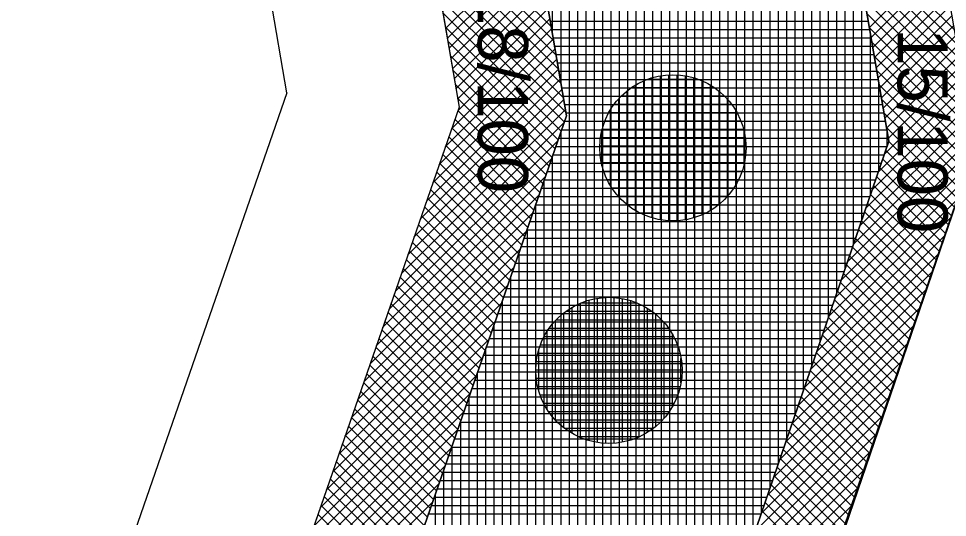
# Model space of a CAD drawing. Extents: x -565346 to -564154, y -1097386 to -1095620.
# Drawn here: x -564193.91 to -564171.69, y -1096311 to -1096299.05 of the extents above; entities that cross this region are included whole.
import ezdxf

# ---------------------------------------------------------------- set-up
doc = ezdxf.new("R2010")
doc.units = 0
for name, color, linetype in [('Vrstva 1', 7, 'Continuous'), ('Vrstva 13', 7, 'Continuous'), ('Vrstva 40', 7, 'Continuous'), ('Vrstva 41', 7, 'Continuous'), ('Vrstva 42', 7, 'Continuous'), ('Vrstva 43', 7, 'Continuous'), ('Vrstva 44', 7, 'Continuous')]:
    doc.layers.add(name, color=color, linetype=linetype)

msp = doc.modelspace()

# ---------------------------------------------------------------- linework, layer by layer
at = {"layer": 'Vrstva 1'}
for p, q in [((-564189.19, -1096267.23), (-564183.37, -1096301.17)), ((-564187.49, -1096300.83), (-564193.07, -1096268.27)), ((-564187.49, -1096300.83), (-564202.39, -1096343.85)), ((-564183.37, -1096301.17), (-564225.11, -1096421.68))]:
    msp.add_line(p, q, dxfattribs=at)
at = {"layer": 'Vrstva 13'}
msp.add_line((-564171.03, -1096302.15), (-564215.39, -1096431.76), dxfattribs=at)
at = {"layer": 'Vrstva 41'}
for points in [[(-564215.226, -1096425.104), (-564213.26, -1096425.74), (-564190.01, -1096357.19), (-564171.03, -1096302.15), (-564177.55, -1096264.11), (-564190.98, -1096227.75), (-564194.264, -1096223.181), (-564195.888, -1096224.348), (-564192.762, -1096228.697), (-564179.49, -1096264.63), (-564173.087, -1096301.985)], [(-564225.11, -1096421.68), (-564222.748, -1096422.498), (-564180.797, -1096301.38), (-564186.765, -1096266.582), (-564199.442, -1096232.246), (-564201.974, -1096228.723), (-564204.005, -1096230.182), (-564201.67, -1096233.43), (-564189.19, -1096267.23), (-564183.37, -1096301.17)]]:
    msp.add_lwpolyline(points, close=True, dxfattribs=at)
at = {"layer": 'Vrstva 42'}
for p, q in [((-564184.226, -1096296.179), (-564181.164, -1096299.241)), ((-564184.167, -1096296.52), (-564181.105, -1096299.582)), ((-564184.109, -1096296.862), (-564181.047, -1096299.924)), ((-564173.962, -1096296.881), (-564171.513, -1096299.329)), ((-564184.05, -1096297.203), (-564180.988, -1096300.265)), ((-564181.527, -1096297.122), (-564183.693, -1096299.287)), ((-564173.903, -1096297.222), (-564171.455, -1096299.67)), ((-564181.486, -1096297.363), (-564183.651, -1096299.529)), ((-564183.992, -1096297.545), (-564180.93, -1096300.607)), ((-564181.445, -1096297.604), (-564183.61, -1096299.77)), ((-564173.845, -1096297.563), (-564171.396, -1096300.012)), ((-564171.822, -1096297.529), (-564173.554, -1096299.261)), ((-564183.933, -1096297.886), (-564180.871, -1096300.948)), ((-564181.403, -1096297.846), (-564183.569, -1096300.011)), ((-564171.781, -1096297.77), (-564173.513, -1096299.502)), ((-564181.362, -1096298.087), (-564183.527, -1096300.253)), ((-564173.786, -1096297.905), (-564171.338, -1096300.353)), ((-564171.739, -1096298.012), (-564173.471, -1096299.744)), ((-564183.875, -1096298.227), (-564180.813, -1096301.289)), ((-564181.32, -1096298.329), (-564183.486, -1096300.494)), ((-564173.728, -1096298.246), (-564171.279, -1096300.695)), ((-564171.698, -1096298.253), (-564173.43, -1096299.985)), ((-564183.816, -1096298.569), (-564180.85, -1096301.534)), ((-564181.279, -1096298.57), (-564183.444, -1096300.736)), ((-564171.657, -1096298.495), (-564173.388, -1096300.227)), ((-564173.669, -1096298.587), (-564171.221, -1096301.036)), ((-564171.615, -1096298.736), (-564173.347, -1096300.468)), ((-564183.758, -1096298.91), (-564180.923, -1096301.744)), ((-564181.237, -1096298.812), (-564183.403, -1096300.977)), ((-564173.611, -1096298.929), (-564171.162, -1096301.377)), ((-564171.574, -1096298.978), (-564173.306, -1096300.709)), ((-564181.196, -1096299.053), (-564183.4, -1096301.257)), ((-564171.532, -1096299.219), (-564173.264, -1096300.951)), ((-564183.699, -1096299.251), (-564180.996, -1096301.954)), ((-564181.155, -1096299.295), (-564183.55, -1096301.69)), ((-564173.552, -1096299.27), (-564171.104, -1096301.719)), ((-564181.113, -1096299.536), (-564183.7, -1096302.123)), ((-564183.64, -1096299.593), (-564181.069, -1096302.165)), ((-564173.494, -1096299.612), (-564171.045, -1096302.06)), ((-564171.491, -1096299.461), (-564173.223, -1096301.192)), ((-564181.072, -1096299.777), (-564183.85, -1096302.555)), ((-564171.45, -1096299.702), (-564173.181, -1096301.434)), ((-564181.03, -1096300.019), (-564184, -1096302.988)), ((-564183.582, -1096299.934), (-564181.142, -1096302.375)), ((-564173.435, -1096299.953), (-564171.083, -1096302.305)), ((-564171.408, -1096299.943), (-564173.14, -1096301.675)), ((-564180.989, -1096300.26), (-564184.15, -1096303.421)), ((-564183.523, -1096300.276), (-564181.214, -1096302.585)), ((-564173.377, -1096300.294), (-564171.156, -1096302.515)), ((-564171.367, -1096300.185), (-564173.099, -1096301.917)), ((-564180.948, -1096300.502), (-564184.299, -1096303.854)), ((-564171.325, -1096300.426), (-564173.193, -1096302.293)), ((-564180.906, -1096300.743), (-564184.449, -1096304.286)), ((-564183.465, -1096300.617), (-564181.287, -1096302.795)), ((-564171.284, -1096300.668), (-564173.34, -1096302.724)), ((-564173.318, -1096300.636), (-564171.228, -1096302.725)), ((-564180.865, -1096300.985), (-564184.599, -1096304.719)), ((-564183.406, -1096300.958), (-564181.36, -1096303.005)), ((-564171.243, -1096300.909), (-564173.487, -1096303.154)), ((-564173.26, -1096300.977), (-564171.301, -1096302.936)), ((-564180.823, -1096301.226), (-564184.749, -1096305.152)), ((-564171.201, -1096301.151), (-564173.634, -1096303.584)), ((-564183.398, -1096301.25), (-564181.433, -1096303.215)), ((-564171.16, -1096301.392), (-564173.781, -1096304.014)), ((-564173.201, -1096301.318), (-564171.373, -1096303.146)), ((-564180.851, -1096301.537), (-564184.899, -1096305.584)), ((-564183.543, -1096301.67), (-564181.578, -1096303.635)), ((-564183.47, -1096301.46), (-564181.505, -1096303.425)), ((-564171.119, -1096301.634), (-564173.928, -1096304.444)), ((-564173.143, -1096301.66), (-564171.446, -1096303.356)), ((-564183.616, -1096301.88), (-564181.651, -1096303.845)), ((-564171.077, -1096301.875), (-564174.076, -1096304.874)), ((-564181.001, -1096301.969), (-564185.049, -1096306.017)), ((-564183.689, -1096302.09), (-564181.724, -1096304.055)), ((-564171.036, -1096302.117), (-564174.223, -1096305.304)), ((-564173.09, -1096301.995), (-564171.519, -1096303.567)), ((-564183.761, -1096302.3), (-564181.796, -1096304.265)), ((-564173.163, -1096302.206), (-564171.591, -1096303.777)), ((-564181.151, -1096302.402), (-564185.199, -1096306.45)), ((-564183.834, -1096302.51), (-564181.869, -1096304.475)), ((-564171.158, -1096302.522), (-564174.37, -1096305.734)), ((-564173.235, -1096302.416), (-564171.664, -1096303.987)), ((-564183.907, -1096302.72), (-564181.942, -1096304.685)), ((-564173.307, -1096302.627), (-564171.736, -1096304.198)), ((-564181.301, -1096302.835), (-564185.349, -1096306.883)), ((-564183.98, -1096302.93), (-564182.015, -1096304.896)), ((-564171.307, -1096302.954), (-564174.517, -1096306.164)), ((-564173.379, -1096302.838), (-564171.809, -1096304.408)), ((-564184.053, -1096303.141), (-564182.087, -1096305.106)), ((-564173.451, -1096303.048), (-564171.881, -1096304.618)), ((-564181.451, -1096303.268), (-564185.499, -1096307.315)), ((-564184.125, -1096303.351), (-564182.16, -1096305.316)), ((-564171.456, -1096303.385), (-564174.664, -1096306.594)), ((-564173.523, -1096303.259), (-564171.954, -1096304.829)), ((-564184.198, -1096303.561), (-564182.233, -1096305.526)), ((-564173.667, -1096303.681), (-564172.099, -1096305.249)), ((-564173.595, -1096303.47), (-564172.026, -1096305.039)), ((-564181.601, -1096303.7), (-564185.648, -1096307.748)), ((-564184.271, -1096303.771), (-564182.306, -1096305.736)), ((-564171.605, -1096303.817), (-564174.812, -1096307.024)), ((-564173.739, -1096303.891), (-564172.171, -1096305.46)), ((-564184.344, -1096303.981), (-564182.378, -1096305.946)), ((-564173.812, -1096304.102), (-564172.244, -1096305.67)), ((-564181.751, -1096304.133), (-564185.798, -1096308.181)), ((-564184.416, -1096304.191), (-564182.451, -1096306.156)), ((-564171.754, -1096304.249), (-564174.959, -1096307.454)), ((-564173.884, -1096304.313), (-564172.316, -1096305.88)), ((-564181.9, -1096304.566), (-564185.948, -1096308.614)), ((-564184.489, -1096304.401), (-564182.524, -1096306.366)), ((-564173.956, -1096304.524), (-564172.389, -1096306.091)), ((-564184.562, -1096304.611), (-564182.597, -1096306.576)), ((-564171.903, -1096304.68), (-564175.106, -1096307.884)), ((-564174.028, -1096304.734), (-564172.461, -1096306.301)), ((-564182.05, -1096304.999), (-564186.098, -1096309.046)), ((-564184.635, -1096304.821), (-564182.67, -1096306.786)), ((-564174.1, -1096304.945), (-564172.534, -1096306.511)), ((-564184.707, -1096305.031), (-564182.742, -1096306.996)), ((-564172.051, -1096305.112), (-564175.253, -1096308.314)), ((-564174.172, -1096305.156), (-564172.606, -1096306.721)), ((-564182.2, -1096305.431), (-564186.248, -1096309.479)), ((-564184.853, -1096305.451), (-564182.888, -1096307.417)), ((-564184.78, -1096305.241), (-564182.815, -1096307.206)), ((-564174.244, -1096305.366), (-564172.679, -1096306.932)), ((-564184.926, -1096305.662), (-564182.961, -1096307.627)), ((-564172.2, -1096305.544), (-564175.4, -1096308.744)), ((-564174.316, -1096305.577), (-564172.751, -1096307.142)), ((-564182.35, -1096305.864), (-564186.398, -1096309.912)), ((-564184.998, -1096305.872), (-564183.033, -1096307.837)), ((-564174.389, -1096305.788), (-564172.824, -1096307.352)), ((-564185.071, -1096306.082), (-564183.106, -1096308.047)), ((-564172.349, -1096305.976), (-564175.547, -1096309.174)), ((-564174.461, -1096305.999), (-564172.897, -1096307.563)), ((-564182.5, -1096306.297), (-564186.548, -1096310.344)), ((-564185.144, -1096306.292), (-564183.179, -1096308.257)), ((-564174.533, -1096306.209), (-564172.969, -1096307.773)), ((-564185.217, -1096306.502), (-564183.252, -1096308.467)), ((-564172.498, -1096306.407), (-564175.695, -1096309.604)), ((-564174.605, -1096306.42), (-564173.042, -1096307.983)), ((-564182.65, -1096306.729), (-564186.698, -1096310.777)), ((-564185.29, -1096306.712), (-564183.324, -1096308.677)), ((-564174.677, -1096306.631), (-564173.114, -1096308.194)), ((-564185.362, -1096306.922), (-564183.397, -1096308.887)), ((-564172.647, -1096306.839), (-564175.842, -1096310.034)), ((-564174.749, -1096306.841), (-564173.187, -1096308.404)), ((-564182.8, -1096307.162), (-564186.847, -1096311.21)), ((-564185.435, -1096307.132), (-564183.47, -1096309.097)), ((-564174.821, -1096307.052), (-564173.259, -1096308.614)), ((-564185.508, -1096307.342), (-564183.543, -1096309.307)), ((-564172.796, -1096307.271), (-564175.989, -1096310.464)), ((-564174.893, -1096307.263), (-564173.332, -1096308.825)), ((-564182.95, -1096307.595), (-564186.997, -1096311.643)), ((-564185.581, -1096307.552), (-564183.615, -1096309.517)), ((-564174.966, -1096307.474), (-564173.404, -1096309.035)), ((-564185.653, -1096307.762), (-564183.688, -1096309.727)), ((-564172.945, -1096307.702), (-564176.136, -1096310.894)), ((-564175.11, -1096307.895), (-564173.549, -1096309.456)), ((-564175.038, -1096307.684), (-564173.477, -1096309.245)), ((-564183.099, -1096308.028), (-564187.147, -1096312.075)), ((-564185.726, -1096307.972), (-564183.761, -1096309.937)), ((-564175.182, -1096308.106), (-564173.622, -1096309.666)), ((-564185.799, -1096308.182), (-564183.834, -1096310.148)), ((-564173.094, -1096308.134), (-564176.283, -1096311.324)), ((-564175.254, -1096308.317), (-564173.694, -1096309.876)), ((-564183.249, -1096308.46), (-564187.297, -1096312.508)), ((-564185.872, -1096308.393), (-564183.907, -1096310.358)), ((-564173.242, -1096308.566), (-564176.431, -1096311.754)), ((-564175.326, -1096308.527), (-564173.767, -1096310.087)), ((-564185.944, -1096308.603), (-564183.979, -1096310.568)), ((-564175.398, -1096308.738), (-564173.839, -1096310.297)), ((-564183.399, -1096308.893), (-564187.447, -1096312.941)), ((-564186.017, -1096308.813), (-564184.052, -1096310.778)), ((-564173.391, -1096308.998), (-564176.578, -1096312.184)), ((-564175.47, -1096308.949), (-564173.912, -1096310.507)), ((-564186.163, -1096309.233), (-564184.198, -1096311.198)), ((-564186.09, -1096309.023), (-564184.125, -1096310.988)), ((-564175.543, -1096309.159), (-564173.984, -1096310.718)), ((-564183.549, -1096309.326), (-564187.597, -1096313.373)), ((-564186.235, -1096309.443), (-564184.27, -1096311.408)), ((-564173.54, -1096309.429), (-564176.725, -1096312.614)), ((-564175.615, -1096309.37), (-564174.057, -1096310.928)), ((-564186.308, -1096309.653), (-564184.343, -1096311.618)), ((-564175.687, -1096309.581), (-564174.129, -1096311.138)), ((-564183.699, -1096309.758), (-564187.747, -1096313.806)), ((-564186.381, -1096309.863), (-564184.416, -1096311.828)), ((-564173.689, -1096309.861), (-564176.872, -1096313.044)), ((-564175.759, -1096309.792), (-564174.202, -1096311.348)), ((-564186.454, -1096310.073), (-564184.489, -1096312.038)), ((-564175.831, -1096310.002), (-564174.275, -1096311.559)), ((-564183.849, -1096310.191), (-564187.897, -1096314.239)), ((-564186.526, -1096310.283), (-564184.561, -1096312.248)), ((-564173.838, -1096310.293), (-564177.019, -1096313.474)), ((-564175.903, -1096310.213), (-564174.347, -1096311.769)), ((-564186.599, -1096310.493), (-564184.634, -1096312.458)), ((-564175.975, -1096310.424), (-564174.42, -1096311.979)), ((-564183.999, -1096310.624), (-564188.046, -1096314.672)), ((-564186.672, -1096310.703), (-564184.707, -1096312.668)), ((-564173.987, -1096310.724), (-564177.166, -1096313.904)), ((-564176.047, -1096310.634), (-564174.492, -1096312.19)), ((-564186.745, -1096310.913), (-564184.78, -1096312.879)), ((-564176.119, -1096310.845), (-564174.565, -1096312.4))]:
    msp.add_line(p, q, dxfattribs=at)
at = {"layer": 'Vrstva 43'}
for p, q in [((-564181.13, -1096299.438), (-564181.13, -1096260.19)), ((-564180.93, -1096300.605), (-564180.93, -1096260.731)), ((-564180.73, -1096324.316), (-564180.73, -1096261.273)), ((-564180.53, -1096323.731), (-564180.53, -1096261.814)), ((-564180.33, -1096323.147), (-564180.33, -1096262.356)), ((-564180.13, -1096322.563), (-564180.13, -1096262.897)), ((-564179.93, -1096321.978), (-564179.93, -1096263.439)), ((-564179.73, -1096321.394), (-564179.73, -1096263.98)), ((-564179.53, -1096320.81), (-564179.53, -1096264.522)), ((-564179.33, -1096320.225), (-564179.33, -1096265.563)), ((-564179.13, -1096319.641), (-564179.13, -1096266.73)), ((-564178.93, -1096319.057), (-564178.93, -1096267.897)), ((-564178.73, -1096318.472), (-564178.73, -1096269.064)), ((-564178.53, -1096317.888), (-564178.53, -1096270.231)), ((-564178.33, -1096317.304), (-564178.33, -1096271.397)), ((-564178.13, -1096316.719), (-564178.13, -1096272.564)), ((-564177.93, -1096316.135), (-564177.93, -1096273.731)), ((-564177.73, -1096315.551), (-564177.73, -1096274.898)), ((-564177.53, -1096314.966), (-564177.53, -1096276.065)), ((-564177.33, -1096314.382), (-564177.33, -1096277.231)), ((-564177.13, -1096313.798), (-564177.13, -1096278.398)), ((-564176.93, -1096313.213), (-564176.93, -1096279.565)), ((-564176.73, -1096312.629), (-564176.73, -1096280.732)), ((-564176.53, -1096312.045), (-564176.53, -1096281.899)), ((-564176.33, -1096311.46), (-564176.33, -1096283.065)), ((-564176.13, -1096310.876), (-564176.13, -1096284.232)), ((-564175.93, -1096310.291), (-564175.93, -1096285.399)), ((-564175.73, -1096309.707), (-564175.73, -1096286.566)), ((-564175.53, -1096309.123), (-564175.53, -1096287.733)), ((-564175.33, -1096308.538), (-564175.33, -1096288.899)), ((-564175.13, -1096307.954), (-564175.13, -1096290.066)), ((-564174.93, -1096307.37), (-564174.93, -1096291.233)), ((-564174.73, -1096306.785), (-564174.73, -1096292.4)), ((-564174.53, -1096306.201), (-564174.53, -1096293.567)), ((-564174.33, -1096305.617), (-564174.33, -1096294.733)), ((-564174.13, -1096305.032), (-564174.13, -1096295.9)), ((-564173.93, -1096304.448), (-564173.93, -1096297.067)), ((-564173.73, -1096303.864), (-564173.73, -1096298.234)), ((-564181.186, -1096299.11), (-564173.58, -1096299.11)), ((-564181.152, -1096299.31), (-564173.546, -1096299.31)), ((-564173.53, -1096303.279), (-564173.53, -1096299.401)), ((-564181.118, -1096299.51), (-564173.511, -1096299.51)), ((-564181.083, -1096299.71), (-564173.477, -1096299.71)), ((-564181.049, -1096299.91), (-564173.443, -1096299.91)), ((-564181.015, -1096300.11), (-564173.408, -1096300.11)), ((-564180.981, -1096300.31), (-564173.374, -1096300.31)), ((-564180.946, -1096300.51), (-564173.34, -1096300.51)), ((-564173.33, -1096302.695), (-564173.33, -1096300.567)), ((-564180.912, -1096300.71), (-564173.306, -1096300.71)), ((-564180.878, -1096300.91), (-564173.271, -1096300.91)), ((-564180.843, -1096301.11), (-564173.237, -1096301.11)), ((-564180.809, -1096301.31), (-564173.203, -1096301.31)), ((-564180.842, -1096301.51), (-564173.168, -1096301.51)), ((-564180.93, -1096324.9), (-564180.93, -1096301.764)), ((-564180.911, -1096301.71), (-564173.134, -1096301.71)), ((-564173.13, -1096302.111), (-564173.13, -1096301.734)), ((-564181.05, -1096302.11), (-564173.13, -1096302.11)), ((-564180.981, -1096301.91), (-564173.1, -1096301.91)), ((-564181.13, -1096325.485), (-564181.13, -1096302.341)), ((-564181.119, -1096302.31), (-564173.198, -1096302.31)), ((-564181.188, -1096302.51), (-564173.267, -1096302.51)), ((-564181.258, -1096302.71), (-564173.335, -1096302.71)), ((-564181.33, -1096326.069), (-564181.33, -1096302.919)), ((-564181.327, -1096302.91), (-564173.404, -1096302.91)), ((-564181.396, -1096303.11), (-564173.472, -1096303.11)), ((-564181.465, -1096303.31), (-564173.54, -1096303.31)), ((-564181.535, -1096303.51), (-564173.609, -1096303.51)), ((-564181.53, -1096326.653), (-564181.53, -1096303.496)), ((-564181.604, -1096303.71), (-564173.677, -1096303.71)), ((-564181.743, -1096304.11), (-564173.814, -1096304.11)), ((-564181.73, -1096327.238), (-564181.73, -1096304.074)), ((-564181.673, -1096303.91), (-564173.746, -1096303.91)), ((-564181.812, -1096304.31), (-564173.883, -1096304.31)), ((-564181.881, -1096304.51), (-564173.951, -1096304.51)), ((-564181.95, -1096304.71), (-564174.02, -1096304.71)), ((-564181.93, -1096327.822), (-564181.93, -1096304.651)), ((-564182.02, -1096304.91), (-564174.088, -1096304.91)), ((-564182.13, -1096328.406), (-564182.13, -1096305.229)), ((-564182.089, -1096305.11), (-564174.157, -1096305.11)), ((-564182.158, -1096305.31), (-564174.225, -1096305.31)), ((-564182.227, -1096305.51), (-564174.293, -1096305.51)), ((-564182.33, -1096328.991), (-564182.33, -1096305.806)), ((-564182.297, -1096305.71), (-564174.362, -1096305.71)), ((-564182.435, -1096306.11), (-564174.499, -1096306.11)), ((-564182.366, -1096305.91), (-564174.43, -1096305.91)), ((-564182.505, -1096306.31), (-564174.567, -1096306.31)), ((-564182.574, -1096306.51), (-564174.636, -1096306.51)), ((-564182.53, -1096329.575), (-564182.53, -1096306.383)), ((-564182.643, -1096306.71), (-564174.704, -1096306.71)), ((-564182.73, -1096330.159), (-564182.73, -1096306.961)), ((-564182.712, -1096306.91), (-564174.773, -1096306.91)), ((-564182.782, -1096307.11), (-564174.841, -1096307.11)), ((-564182.851, -1096307.31), (-564174.91, -1096307.31)), ((-564182.93, -1096330.744), (-564182.93, -1096307.538)), ((-564182.92, -1096307.51), (-564174.978, -1096307.51)), ((-564182.989, -1096307.71), (-564175.046, -1096307.71)), ((-564183.13, -1096331.328), (-564183.13, -1096308.116)), ((-564183.128, -1096308.11), (-564175.183, -1096308.11)), ((-564183.059, -1096307.91), (-564175.115, -1096307.91)), ((-564183.197, -1096308.31), (-564175.252, -1096308.31)), ((-564183.267, -1096308.51), (-564175.32, -1096308.51)), ((-564183.336, -1096308.71), (-564175.389, -1096308.71)), ((-564183.33, -1096331.912), (-564183.33, -1096308.693)), ((-564183.405, -1096308.91), (-564175.457, -1096308.91)), ((-564183.474, -1096309.11), (-564175.526, -1096309.11)), ((-564183.544, -1096309.31), (-564175.594, -1096309.31)), ((-564183.53, -1096332.497), (-564183.53, -1096309.271)), ((-564183.613, -1096309.51), (-564175.663, -1096309.51)), ((-564183.73, -1096333.081), (-564183.73, -1096309.848)), ((-564183.682, -1096309.71), (-564175.731, -1096309.71)), ((-564183.821, -1096310.11), (-564175.868, -1096310.11)), ((-564183.751, -1096309.91), (-564175.799, -1096309.91)), ((-564183.89, -1096310.31), (-564175.936, -1096310.31)), ((-564183.959, -1096310.51), (-564176.005, -1096310.51)), ((-564183.93, -1096333.665), (-564183.93, -1096310.425)), ((-564184.029, -1096310.71), (-564176.073, -1096310.71)), ((-564184.098, -1096310.91), (-564176.142, -1096310.91))]:
    msp.add_line(p, q, dxfattribs=at)
msp.add_lwpolyline([(-564186.765, -1096266.582), (-564180.797, -1096301.38), (-564222.748, -1096422.498), (-564225.11, -1096421.68), (-564223.32, -1096427.69), (-564219.79, -1096430.8), (-564216.6, -1096431.71), (-564215.39, -1096431.76), (-564213.26, -1096425.74), (-564215.226, -1096425.104), (-564173.087, -1096301.985), (-564179.49, -1096264.63)], dxfattribs=at)
at = {"layer": 'Vrstva 44'}
for p, q in [((-564178.95, -1096303.748), (-564178.95, -1096300.54)), ((-564178.85, -1096300.5), (-564177.66, -1096300.5)), ((-564178.75, -1096303.822), (-564178.75, -1096300.467)), ((-564178.55, -1096303.867), (-564178.55, -1096300.42)), ((-564178.35, -1096303.89), (-564178.35, -1096300.398)), ((-564178.15, -1096303.89), (-564178.15, -1096300.399)), ((-564177.95, -1096303.866), (-564177.95, -1096300.422)), ((-564177.75, -1096303.818), (-564177.75, -1096300.469)), ((-564177.55, -1096303.744), (-564177.55, -1096300.543)), ((-564179.35, -1096303.508), (-564179.35, -1096300.781)), ((-564179.239, -1096300.7), (-564177.267, -1096300.7)), ((-564179.15, -1096303.645), (-564179.15, -1096300.642)), ((-564177.35, -1096303.642), (-564177.35, -1096300.648)), ((-564177.15, -1096303.499), (-564177.15, -1096300.786)), ((-564179.55, -1096303.318), (-564179.55, -1096300.969)), ((-564179.483, -1096300.9), (-564177.023, -1096300.9)), ((-564176.95, -1096303.31), (-564176.95, -1096300.98)), ((-564179.658, -1096301.1), (-564176.852, -1096301.1)), ((-564179.785, -1096301.3), (-564176.721, -1096301.3)), ((-564179.75, -1096303.049), (-564179.75, -1096301.237)), ((-564176.75, -1096303.037), (-564176.75, -1096301.253)), ((-564179.879, -1096301.5), (-564176.629, -1096301.5)), ((-564179.986, -1096301.9), (-564176.522, -1096301.9)), ((-564179.95, -1096302.572), (-564179.95, -1096301.713)), ((-564179.946, -1096301.7), (-564176.563, -1096301.7)), ((-564176.55, -1096302.534), (-564176.55, -1096301.749)), ((-564180.002, -1096302.1), (-564176.505, -1096302.1)), ((-564179.995, -1096302.3), (-564176.512, -1096302.3)), ((-564179.966, -1096302.5), (-564176.543, -1096302.5)), ((-564179.913, -1096302.7), (-564176.597, -1096302.7)), ((-564179.831, -1096302.9), (-564176.676, -1096302.9)), ((-564179.718, -1096303.1), (-564176.79, -1096303.1)), ((-564179.567, -1096303.3), (-564176.942, -1096303.3)), ((-564179.359, -1096303.5), (-564177.151, -1096303.5)), ((-564179.055, -1096303.7), (-564177.457, -1096303.7)), ((-564180.46, -1096309.087), (-564180.46, -1096305.862)), ((-564180.456, -1096305.86), (-564179.108, -1096305.86)), ((-564180.26, -1096309.158), (-564180.26, -1096305.79)), ((-564180.06, -1096309.2), (-564180.06, -1096305.747)), ((-564179.86, -1096309.221), (-564179.86, -1096305.728)), ((-564179.66, -1096309.219), (-564179.66, -1096305.73)), ((-564179.46, -1096309.192), (-564179.46, -1096305.756)), ((-564179.26, -1096309.142), (-564179.26, -1096305.805)), ((-564179.06, -1096309.066), (-564179.06, -1096305.883)), ((-564180.86, -1096308.854), (-564180.86, -1096306.094)), ((-564180.813, -1096306.06), (-564178.756, -1096306.06)), ((-564180.66, -1096308.987), (-564180.66, -1096305.961)), ((-564178.86, -1096308.959), (-564178.86, -1096305.99)), ((-564181.06, -1096308.669), (-564181.06, -1096306.279)), ((-564181.042, -1096306.26), (-564178.526, -1096306.26)), ((-564178.66, -1096308.813), (-564178.66, -1096306.134)), ((-564178.46, -1096308.616), (-564178.46, -1096306.332)), ((-564181.26, -1096308.411), (-564181.26, -1096306.537)), ((-564181.21, -1096306.46), (-564178.359, -1096306.46)), ((-564181.331, -1096306.66), (-564178.237, -1096306.66)), ((-564178.26, -1096308.33), (-564178.26, -1096306.615)), ((-564181.46, -1096307.971), (-564181.46, -1096306.977)), ((-564181.422, -1096306.86), (-564178.148, -1096306.86)), ((-564181.484, -1096307.06), (-564178.085, -1096307.06)), ((-564178.06, -1096307.771), (-564178.06, -1096307.186)), ((-564181.519, -1096307.26), (-564178.047, -1096307.26)), ((-564181.532, -1096307.46), (-564178.035, -1096307.46)), ((-564181.523, -1096307.66), (-564178.046, -1096307.66)), ((-564181.49, -1096307.86), (-564178.079, -1096307.86)), ((-564181.432, -1096308.06), (-564178.136, -1096308.06)), ((-564181.346, -1096308.26), (-564178.222, -1096308.26)), ((-564181.229, -1096308.46), (-564178.341, -1096308.46)), ((-564181.068, -1096308.66), (-564178.498, -1096308.66)), ((-564180.851, -1096308.86), (-564178.717, -1096308.86)), ((-564180.519, -1096309.06), (-564179.047, -1096309.06))]:
    msp.add_line(p, q, dxfattribs=at)
for centre in [(-564178.254, -1096302.144), (-564179.784, -1096307.474)]:
    msp.add_circle(centre, 1.75, dxfattribs=at)

# ---------------------------------------------------------------- texts
at = {"layer": 'Vrstva 40'}
for s, p in [('18/100', (-564182.92, -1096298.32)), ('15/100', (-564172.88, -1096299.28))]:
    msp.add_text(s, height=1.2, rotation=270, dxfattribs=at).set_placement(p)

doc.saveas('drawing.dxf')
